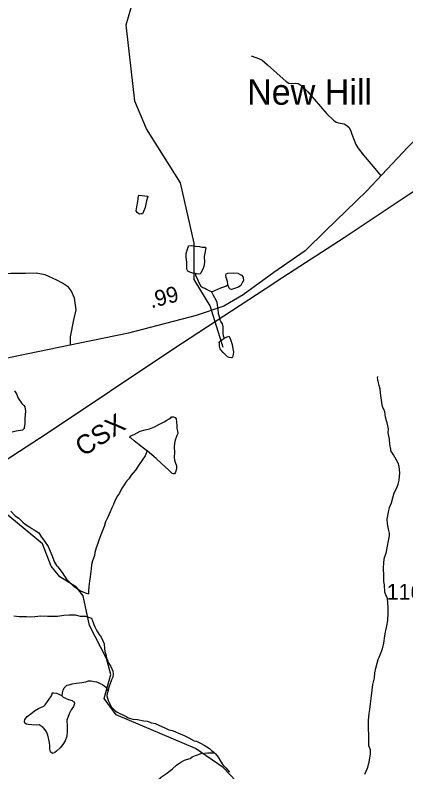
# Model space of a CAD drawing. Extents: x 2001466 to 2224147, y 644118 to 847247.
# Drawn here: x 2015726 to 2018793, y 697641 to 703581 of the extents above; entities that cross this region are included whole.
import ezdxf

# ---------------------------------------------------------------- set-up
doc = ezdxf.new("R2010")
doc.units = 0
for name, color, linetype in [('Exist Civil Demographics Community Label', 7, 'Continuous'), ('Exist Hydrographic Creek Single Shore', 7, 'Continuous'), ('Exist Hydrographic Misc Water Feature', 7, 'Continuous'), ('Exist Railroad Mainline', 7, 'Continuous'), ('Exist Railroad Mainline Label', 7, 'Continuous'), ('Exist Road Non-System Type 51', 7, 'Continuous'), ('Exist Road Non-System Type 51 Label', 7, 'Continuous'), ('Exist Road Secondary Mileage Hundredths English Label', 7, 'Continuous'), ('Exist Road Secondary Type 51 Attributed', 7, 'Continuous'), ('Exist Road Secondary Type 51 Number Label', 7, 'Continuous')]:
    doc.layers.add(name, color=color, linetype=linetype)

msp = doc.modelspace()

# ---------------------------------------------------------------- linework, layer by layer
at = {"layer": 'Exist Hydrographic Creek Single Shore'}
msp.add_lwpolyline([(2018092.5, 697131.9), (2017834.5, 697232.3), (2017709.4, 697307), (2017359.6, 697675.1), (2017142.5, 697823.8), (2016517.5, 698089.3), (2016425.6, 698215.7), (2016475.6, 698405), (2016442.6, 698530.4), (2016308.5, 698789), (2016258.5, 699023.1), (2016208.6, 699089.7), (2016075.6, 699171.1), (2016008.5, 699254.6), (2015941.7, 699429.8), (2015608.7, 699705.6), (2015341.7, 699980.1), (2015308.7, 700079.2), (2015383.5, 700264.7), (2015624.7, 700637.1)], dxfattribs=at)
at = {"layer": 'Exist Hydrographic Misc Water Feature'}
for points in [[(2017357.6, 700972.6), (2017257.7, 701299.5), (2017131.6, 701505.5), (2017131.6, 701791), (2017023.7, 702265.7), (2016756.8, 702687.8), (2016664.7, 702906.2), (2016597.6, 703504.7), (2016689.7, 703821.1), (2016630.6, 704439.2), (2016546.8, 704637.7), (2016504.7, 704979.8), (2016471.7, 705088.8), (2016238.8, 705313.3), (2015804.7, 705555.1)], [(2016698.1, 702168.2), (2016766.2, 702160.3), (2016756.1, 702124.2), (2016746.1, 702070.2), (2016732.1, 702040.2), (2016724.4, 702022.3), (2016716.2, 702020.2), (2016702.2, 702018.2), (2016696.3, 702020.2), (2016684.2, 702032.2), (2016676.4, 702046.2), (2016680.1, 702076.2), (2016688.1, 702118.2), (2016690.1, 702138.2), (2016694.2, 702162.2), (2016698.1, 702168.2)], [(2017140.4, 701552.5), (2017120.3, 701556.5), (2017096.3, 701562.5), (2017082.4, 701572.5), (2017074.4, 701586.5), (2017072.3, 701606.5), (2017072.3, 701642.5), (2017068.4, 701682.5), (2017068.4, 701710.4), (2017074.2, 701728.5), (2017082.2, 701752.5), (2017086.3, 701764.5), (2017086.3, 701770.5), (2017108.2, 701772.5), (2017140.2, 701768.5), (2017172.2, 701764.5)], [(2017172.2, 701764.5), (2017192.3, 701760.5), (2017216.3, 701758.6), (2017222.2, 701754.6), (2017214.4, 701712.6), (2017210.3, 701686.6), (2017212.4, 701642.6), (2017206.4, 701608.6), (2017198.4, 701586.6), (2017186.3, 701562.6), (2017182.4, 701556.6), (2017176.3, 701548.6), (2017148.4, 701550.5), (2017140.4, 701552.5)], [(2017140.4, 701552.5), (2017142.5, 701540.5), (2017160.5, 701500.5), (2017172.6, 701472.6), (2017184.5, 701452.6), (2017198.4, 701442.6), (2017214.4, 701436.6), (2017228.6, 701430.6), (2017246.4, 701418.6), (2017266.5, 701410.6)], [(2017396.3, 701464.7), (2017396.3, 701468.7), (2017392.4, 701490.7), (2017382.4, 701520.7), (2017378.5, 701540.7), (2017382.4, 701550.7), (2017394.5, 701556.7), (2017440.4, 701558.7), (2017472.4, 701556.7), (2017492.5, 701544.8), (2017502.3, 701538.7), (2017514.4, 701524.8), (2017516.5, 701520.8), (2017518.3, 701498.8), (2017508.5, 701478.8), (2017496.6, 701458.8), (2017478.5, 701446.8), (2017454.5, 701438.8), (2017438.6, 701432.8), (2017424.6, 701426.7), (2017414.6, 701428.7), (2017404.5, 701438.7), (2017400.4, 701454.7), (2017396.3, 701464.7)], [(2017266.5, 701410.6), (2017274.5, 701410.6), (2017292.6, 701418.6), (2017316.5, 701430.6), (2017340.5, 701440.6), (2017364.5, 701448.7), (2017378.5, 701454.7), (2017390.6, 701462.7), (2017396.3, 701464.7)], [(2017266.5, 701410.6), (2017268.6, 701402.6), (2017280.5, 701382.7), (2017304.4, 701340.7), (2017308.5, 701326.7), (2017312.4, 701304.7), (2017316.5, 701274.7), (2017318.6, 701238.7), (2017326.6, 701214.7), (2017332.5, 701188.7), (2017340.5, 701172.7), (2017350.6, 701158.7), (2017356.5, 701134.7), (2017354.7, 701110.7), (2017354.7, 701084.7), (2017358.6, 701064.8), (2017360.8, 701060.8), (2017364.7, 701042.8)], [(2017364.7, 701042.8), (2017372.5, 701046.8), (2017390.8, 701054.8), (2017402.7, 701060.8), (2017412.7, 701042.8), (2017428.7, 700994.7), (2017434.7, 700962.8), (2017438.8, 700938.8), (2017436.7, 700916.8), (2017432.8, 700896.8), (2017428.7, 700890.8), (2017422.8, 700890.8), (2017404.7, 700894.8), (2017392.8, 700898.8), (2017374.8, 700916.8), (2017358.8, 700932.8), (2017340.7, 700954.8), (2017334.8, 700962.7), (2017330.7, 700982.7), (2017328.6, 700998.7), (2017328.6, 701006.7), (2017326.8, 701012.7), (2017330.7, 701018.7), (2017354.7, 701036.8), (2017364.7, 701042.8)], [(2018470.6, 697623.8), (2018492.5, 697669.9), (2018504.4, 697717.9), (2018514.5, 697781.9), (2018514.5, 697813.8), (2018502.4, 697845.9), (2018502.4, 697859.9), (2018502.4, 697879.8), (2018502.4, 697933.8), (2018500.3, 697979.9), (2018500.3, 698043.8), (2018504.2, 698097.8), (2018510.2, 698129.9), (2018516.1, 698173.8), (2018524.1, 698237.9), (2018533.9, 698327.8), (2018546, 698377.8), (2018549.9, 698417.9), (2018556.1, 698453.8), (2018566.1, 698493.8), (2018576, 698521.9), (2018592, 698559.9), (2018608, 698605.8), (2018619.9, 698651.8), (2018627.9, 698707.8), (2018633.8, 698737.8), (2018643.8, 698787.9), (2018649.8, 698827.9), (2018653.9, 698889.8), (2018653.7, 698919.8), (2018653.7, 698929.9), (2018651.6, 698965.8), (2018647.7, 699003.8), (2018637.7, 699023.8), (2018627.6, 699051.8), (2018623.8, 699107.8), (2018619.7, 699135.7), (2018619.7, 699187.8), (2018617.6, 699235.7), (2018619.7, 699285.7), (2018625.6, 699323.7), (2018637.5, 699357.7), (2018647.5, 699411.7), (2018657.4, 699453.7), (2018663.5, 699493.7), (2018663.5, 699515.7), (2018657.4, 699545.7), (2018651.2, 699575.7), (2018649.4, 699587.7), (2018645.3, 699623.7), (2018657.4, 699679.7), (2018665.4, 699715.7), (2018679.3, 699753.7), (2018691.2, 699791.7), (2018701.3, 699831.7), (2018721.2, 699869.7), (2018731.2, 699899.7), (2018741, 699931.8), (2018745.1, 699987.7), (2018739, 700037.7), (2018731, 700063.7), (2018717.1, 700093.7), (2018695.1, 700129.7), (2018683, 700151.7), (2018675, 700159.7), (2018675, 700173.7), (2018667, 700211.6), (2018662.9, 700253.7), (2018654.9, 700301.6), (2018657, 700333.7), (2018646.9, 700379.6), (2018640.8, 700397.6), (2018632.8, 700425.6), (2018626.8, 700467.6), (2018618.8, 700487.6), (2018608.8, 700507.5), (2018604.9, 700539.6), (2018596.9, 700595.6), (2018592.8, 700617.5), (2018590.7, 700645.5), (2018582.7, 700673.5), (2018578.6, 700693.5), (2018572.7, 700717.6), (2018568.8, 700733.6)], [(2018568.8, 700733.6), (2018572.7, 700743.6)], [(2015721, 700631.7), (2015735.2, 700607.8), (2015749.1, 700573.8), (2015777.2, 700531.8), (2015793.2, 700517.8), (2015801.2, 700505.8), (2015807.2, 700471.9), (2015801.2, 700415.9), (2015801.2, 700373.8), (2015797.3, 700343.9), (2015797.3, 700335.9), (2015783.4, 700323.9), (2015733.3, 700315.8), (2015701.3, 700307.8)], [(2016761.3, 700160.4), (2016757.2, 700162.5), (2016699.1, 700208.4), (2016661.2, 700240.4), (2016635.2, 700260.4), (2016627.2, 700266.4), (2016631.3, 700278.4), (2016661.2, 700290.4), (2016683.1, 700302.4), (2016707.1, 700316.4), (2016745.3, 700326.4), (2016781.2, 700334.5), (2016819.1, 700350.4), (2016863.2, 700372.5), (2016895.2, 700388.5), (2016917.1, 700400.6), (2016935.1, 700412.5), (2016949.1, 700420.5), (2016953.2, 700426.6), (2016961.2, 700428.6), (2016969.2, 700428.6), (2016981.1, 700422.6), (2016989.1, 700412.5), (2016993.2, 700386.6), (2016995, 700360.6), (2016995, 700338.6), (2017001.2, 700314.6), (2017003.2, 700296.6), (2016995.2, 700280.6), (2016983.1, 700244.6), (2016977.2, 700220.6), (2016973.3, 700190.6), (2016977.2, 700150.6), (2016973.3, 700108.6), (2016977.2, 700086.6), (2016981.3, 700072.6), (2016993.4, 700042.6), (2016993.4, 700020.6), (2016985.4, 699994.7), (2016977.4, 699980.6), (2016969.4, 699980.6), (2016957.3, 699982.7), (2016929.4, 700010.6), (2016875.3, 700060.6), (2016831.4, 700100.5), (2016781.4, 700144.5), (2016761.3, 700160.4)], [(2016761.3, 700160.4), (2016747.3, 700122.5), (2016723.3, 700088.5), (2016699.3, 700052.4), (2016669.4, 700010.4), (2016637.4, 699970.5), (2016617.5, 699942.4), (2016603.4, 699924.4), (2016593.5, 699914.4), (2016581.4, 699894.4), (2016561.5, 699862.4), (2016545.5, 699828.4), (2016529.6, 699808.4), (2016507.6, 699768.4), (2016497.6, 699740.4), (2016485.7, 699712.3), (2016471.5, 699682.4), (2016449.6, 699634.4), (2016435.6, 699604.4), (2016423.7, 699566.3), (2016407.8, 699528.3), (2016397.7, 699500.3), (2016379.7, 699452.3), (2016375.8, 699432.3), (2016361.8, 699398.3), (2016351.8, 699362.3), (2016347.9, 699340.3), (2016333.7, 699296.3), (2016325.7, 699268.3), (2016321.8, 699234.3), (2016314, 699172.3), (2016309.9, 699138.3), (2016304, 699096.3), (2016301.9, 699062.4), (2016301.9, 699038.3)], [(2015691.7, 699687.8), (2015725.8, 699651.9), (2015753.6, 699631.9), (2015785.6, 699601.9), (2015805.7, 699584), (2015833.8, 699566), (2015857.8, 699550), (2015875.6, 699540), (2015889.8, 699530), (2015911.7, 699516), (2015927.7, 699492.1), (2015955.8, 699452), (2015985.8, 699410), (2015999.9, 699372.1), (2016017.7, 699328.1), (2016029.8, 699300.1), (2016033.7, 699288.1), (2016049.9, 699262.1), (2016061.8, 699250.1), (2016094, 699206.2), (2016111.9, 699176.2), (2016129.9, 699154.2), (2016150, 699132.3), (2016174, 699108.3), (2016187.9, 699094.2), (2016203.9, 699086.2), (2016224, 699072.2), (2016243.9, 699060.3), (2016265.9, 699050.3), (2016283.9, 699044.3), (2016301.9, 699038.3)], [(2015716.1, 698866), (2015758.1, 698860), (2015814.1, 698860), (2015844.3, 698858), (2015880.2, 698860), (2015928.1, 698866.1), (2015980.2, 698862.2), (2016032.1, 698864.1), (2016058.1, 698864.1), (2016108, 698872.2), (2016150, 698874.2), (2016198, 698872.3), (2016236.1, 698864.3), (2016264, 698862.4), (2016274.1, 698862.3), (2016278.2, 698862.4), (2016302.2, 698854.4), (2016326.1, 698848.4)], [(2016326.1, 698848.4), (2016332.1, 698826.4), (2016338, 698812.4), (2016344, 698796.4), (2016352, 698778.4), (2016358.1, 698764.4), (2016366.1, 698748.4), (2016386.2, 698718.4), (2016402.2, 698698.4), (2016414.1, 698670.4), (2016424.2, 698646.4), (2016426.2, 698610.4), (2016430.1, 698586.4), (2016436.3, 698562.5), (2016442.2, 698536.5), (2016450.4, 698520.5), (2016456.4, 698500.5), (2016466.4, 698484.5), (2016476.2, 698468.5), (2016484.2, 698450.5), (2016492.2, 698430.5), (2016494.3, 698410.6), (2016492.2, 698384.5), (2016482.4, 698362.5), (2016474.4, 698340.5), (2016464.3, 698314.5), (2016458.4, 698294.5), (2016456.4, 698276.5)], [(2016094.4, 698234.3), (2016096.5, 698262.3), (2016102.4, 698282.3), (2016110.4, 698300.3), (2016132.4, 698320.3), (2016150.4, 698324.3), (2016174.4, 698332.3), (2016206.4, 698336.3), (2016248.4, 698342.3), (2016280.4, 698348.4), (2016300.5, 698354.4), (2016322.5, 698356.4), (2016346.4, 698350.4), (2016364.5, 698346.4), (2016382.3, 698340.5), (2016394.4, 698334.5), (2016410.4, 698326.5), (2016436.5, 698306.5), (2016444.5, 698292.5), (2016450.4, 698282.5), (2016456.4, 698276.5)], [(2016094.4, 698234.3), (2016102.6, 698228.3), (2016120.5, 698218.3), (2016144.5, 698208.3), (2016154.5, 698206.3), (2016172.6, 698200.3), (2016180.6, 698194.3), (2016188.6, 698190.3), (2016192.4, 698176.4), (2016184.5, 698154.4), (2016166.6, 698128.4), (2016148.6, 698096.4), (2016132.6, 698046.4), (2016134.6, 697998.4), (2016134.6, 697958.4), (2016132.6, 697922.3), (2016118.6, 697884.4), (2016100.6, 697854.4), (2016078.6, 697828.3), (2016050.8, 697804.3), (2016036.8, 697792.3), (2016032.7, 697790.3), (2016018.8, 697786.3), (2016006.9, 697794.3), (2016002.8, 697798.3), (2015998.9, 697820.3), (2015998.9, 697844.3), (2015994.6, 697872.2), (2015982.7, 697930.2), (2015970.6, 697956.2), (2015962.6, 697970.2), (2015944.7, 697990.2), (2015914.6, 698010.2), (2015896.8, 698008.2), (2015856.6, 698010.2), (2015828.7, 698012.2), (2015814.7, 698016.1), (2015800.6, 698024.1), (2015798.7, 698036.1), (2015800.6, 698052.1), (2015820.5, 698074.2), (2015848.6, 698096.2), (2015878.5, 698120.2), (2015908.5, 698138.2), (2015938.6, 698150.2), (2015950.5, 698156.3), (2015962.6, 698166.3), (2015980.6, 698192.2), (2015992.5, 698212.2), (2016010.6, 698238.2), (2016016.5, 698252.2), (2016016.5, 698262.2), (2016026.4, 698262.2), (2016050.3, 698258.3), (2016068.4, 698250.3), (2016088.5, 698240.3), (2016094.4, 698234.3)], [(2016456.4, 698276.5), (2016448.4, 698256.5), (2016446.5, 698236.5), (2016456.4, 698200.5), (2016482.6, 698148.6), (2016504.5, 698124.6), (2016526.5, 698110.5), (2016546.6, 698098.5), (2016564.6, 698090.6), (2016582.5, 698082.6), (2016596.6, 698074.6), (2016608.5, 698068.6), (2016630.4, 698060.7), (2016650.5, 698054.7), (2016686.6, 698050.7), (2016734.6, 698040.8), (2016762.5, 698038.8), (2016796.5, 698026.8), (2016824.6, 698020.8), (2016854.6, 698006.8), (2016894.5, 697988.8), (2016932.5, 697970.8), (2016958.5, 697964.9), (2016980.5, 697956.9), (2017012.5, 697942.9), (2017046.5, 697929), (2017088.5, 697907), (2017130.6, 697885), (2017148.6, 697881), (2017180.6, 697865), (2017210.5, 697851), (2017250.5, 697823), (2017266.5, 697809.1), (2017286.6, 697795.1), (2017290.5, 697791.1)], [(2016706.7, 697512.8), (2016720.9, 697514.8), (2016762.7, 697522.8), (2016806.8, 697552.8), (2016832.8, 697566.8), (2016846.8, 697578.9), (2016856.8, 697586.9), (2016866.9, 697594.9), (2016874.9, 697602.9), (2016914.6, 697628.9), (2016960.6, 697664.9), (2016992.6, 697692.9), (2017026.6, 697716.9), (2017054.7, 697732.9), (2017070.7, 697737), (2017098.6, 697746.9), (2017114.6, 697759), (2017140.6, 697769), (2017186.5, 697785.1), (2017234.5, 697791.1), (2017266.7, 697791.1), (2017290.5, 697791.1)], [(2017290.5, 697791.1), (2017298.5, 697781.1), (2017308.5, 697769.1), (2017318.6, 697755.1), (2017338.7, 697725.1), (2017356.7, 697697.1), (2017378.7, 697673.2), (2017408.6, 697637.2)]]:
    msp.add_lwpolyline(points, dxfattribs=at)
at = {"layer": 'Exist Railroad Mainline'}
msp.add_lwpolyline([(2014695.2, 699465.6), (2014957.6, 699637.9), (2015969.1, 700295.6), (2016972.6, 700965.2), (2017688.8, 701433.9), (2017826.9, 701523.3), (2018309.5, 701836.1), (2018810.1, 702169.9), (2019262.5, 702465.7)], dxfattribs=at)
at = {"layer": 'Exist Road Non-System Type 51'}
for points in [[(2017577.4, 703261.1), (2017644.5, 703238.3), (2017665.2, 703227), (2017706.5, 703189.8), (2017854.1, 703059.6), (2017873.7, 703047.2), (2017892.3, 703044.1), (2017929.5, 703047.2), (2017946, 703044.1), (2017967.7, 703031.7), (2018022.4, 702979.1), (2018171, 702806.6), (2018224.9, 702756.6), (2018246.6, 702742.1), (2018264.2, 702735.9), (2018308.5, 702727.6), (2018322, 702720.4), (2018345.7, 702702.8), (2018359.1, 702679.1), (2018367.4, 702646), (2018400.4, 702565.5), (2018416.9, 702539.4), (2018459.3, 702482.6), (2018548.1, 702377.3), (2018597.2, 702320.8)], [(2016097.8, 701476), (2016053.5, 701501.7), (2015960.7, 701543.3), (2015890.4, 701556.1), (2015807.2, 701552.9), (2015765.7, 701552.9), (2015691.3, 701552.9), (2015587, 701548.8), (2015514.7, 701519.9), (2015446.6, 701485.8), (2015403.2, 701472.4), (2015340.3, 701471.3), (2015236, 701469.3)], [(2016159.8, 700990.7), (2016161.2, 701057.1), (2016186, 701190.4), (2016203.5, 701267.9), (2016191.1, 701359.8), (2016168.6, 701415.3), (2016144.7, 701446.6), (2016114.2, 701466.5), (2016097.8, 701476)]]:
    msp.add_lwpolyline(points, dxfattribs=at)
at = {"layer": 'Exist Road Non-System Type 51 Label'}
msp.add_line((2017831.4, 701607.9), (2017829.2, 701610.3), dxfattribs=at)
at = {"layer": 'Exist Road Secondary Type 51 Attributed'}
msp.add_lwpolyline([(2019122.1, 702770.6), (2019002, 702709.1), (2018927.1, 702659.6), (2018809, 702544.6), (2018482.7, 702199.8), (2018165.2, 701891.6), (2018001.7, 701732), (2017756, 701561.2), (2017515.1, 701385.5), (2017363.5, 701297.7), (2017145.8, 701222.7), (2016616.1, 701085.4), (2016233.2, 701005.6), (2015737.8, 700905), (2015517.6, 700857.1), (2015346.9, 700788.4), (2015198.6, 700697.4), (2015069.3, 700582.5), (2014875.5, 700360.6), (2014759, 700218.5)], dxfattribs=at)

# ---------------------------------------------------------------- texts
at = {"layer": 'Exist Civil Demographics Community Label'}
msp.add_text('New Hill', height=200, dxfattribs=at).set_placement((2017546.4, 702878.1))
at = {"layer": 'Exist Railroad Mainline Label'}
msp.add_text('CSX', height=150, rotation=33.1417, dxfattribs=at).set_placement((2016260.1, 700111.2))
at = {"layer": 'Exist Road Secondary Mileage Hundredths English Label'}
msp.add_text('.99', height=125, rotation=14.53211, dxfattribs=at).set_placement((2016794.2, 701279.4))
at = {"layer": 'Exist Road Secondary Type 51 Number Label'}
msp.add_text('1166', height=125, dxfattribs=at).set_placement((2018642.4, 698991.8))

doc.saveas('drawing.dxf')
